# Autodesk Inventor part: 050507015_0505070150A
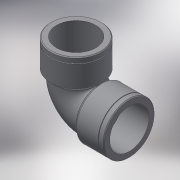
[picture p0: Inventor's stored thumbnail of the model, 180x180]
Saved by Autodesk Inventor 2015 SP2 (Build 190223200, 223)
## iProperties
Created: 2017-05
Part Number: 050507015_0505070150A
Material: Generic
Description: PLASSON THREADED ELBOW 1.1/2"-1.1/2"
Document SubType Name: Modeling
Designer: KIM
Density: 1 g/cm^3
Appearance: Default
Author: KIM
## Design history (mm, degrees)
derived "050507.ipt"
feature "Solid1::050507.ipt"
tag "TaggingFeature1"
body "Solid1"
other parameters: "d0" = 54, "d2" = 0.5, "d3" = 0.5, "d4" = 58.2985, "d5" = 44.845, "d6" = 25, "d7" = 135 deg, "d8" = 28.75, "d9" = 4.79167, "d19" = 0.8969, "d27" = 25, "d30" = 40.3605, "d31" = 51.57175, "d33" = 90 deg, "d35" = 90 deg, "d36" = 90 deg, "d37" = 2.24225, "Rp_" = 44.845, "A_" = 54, "l_2" = 25
